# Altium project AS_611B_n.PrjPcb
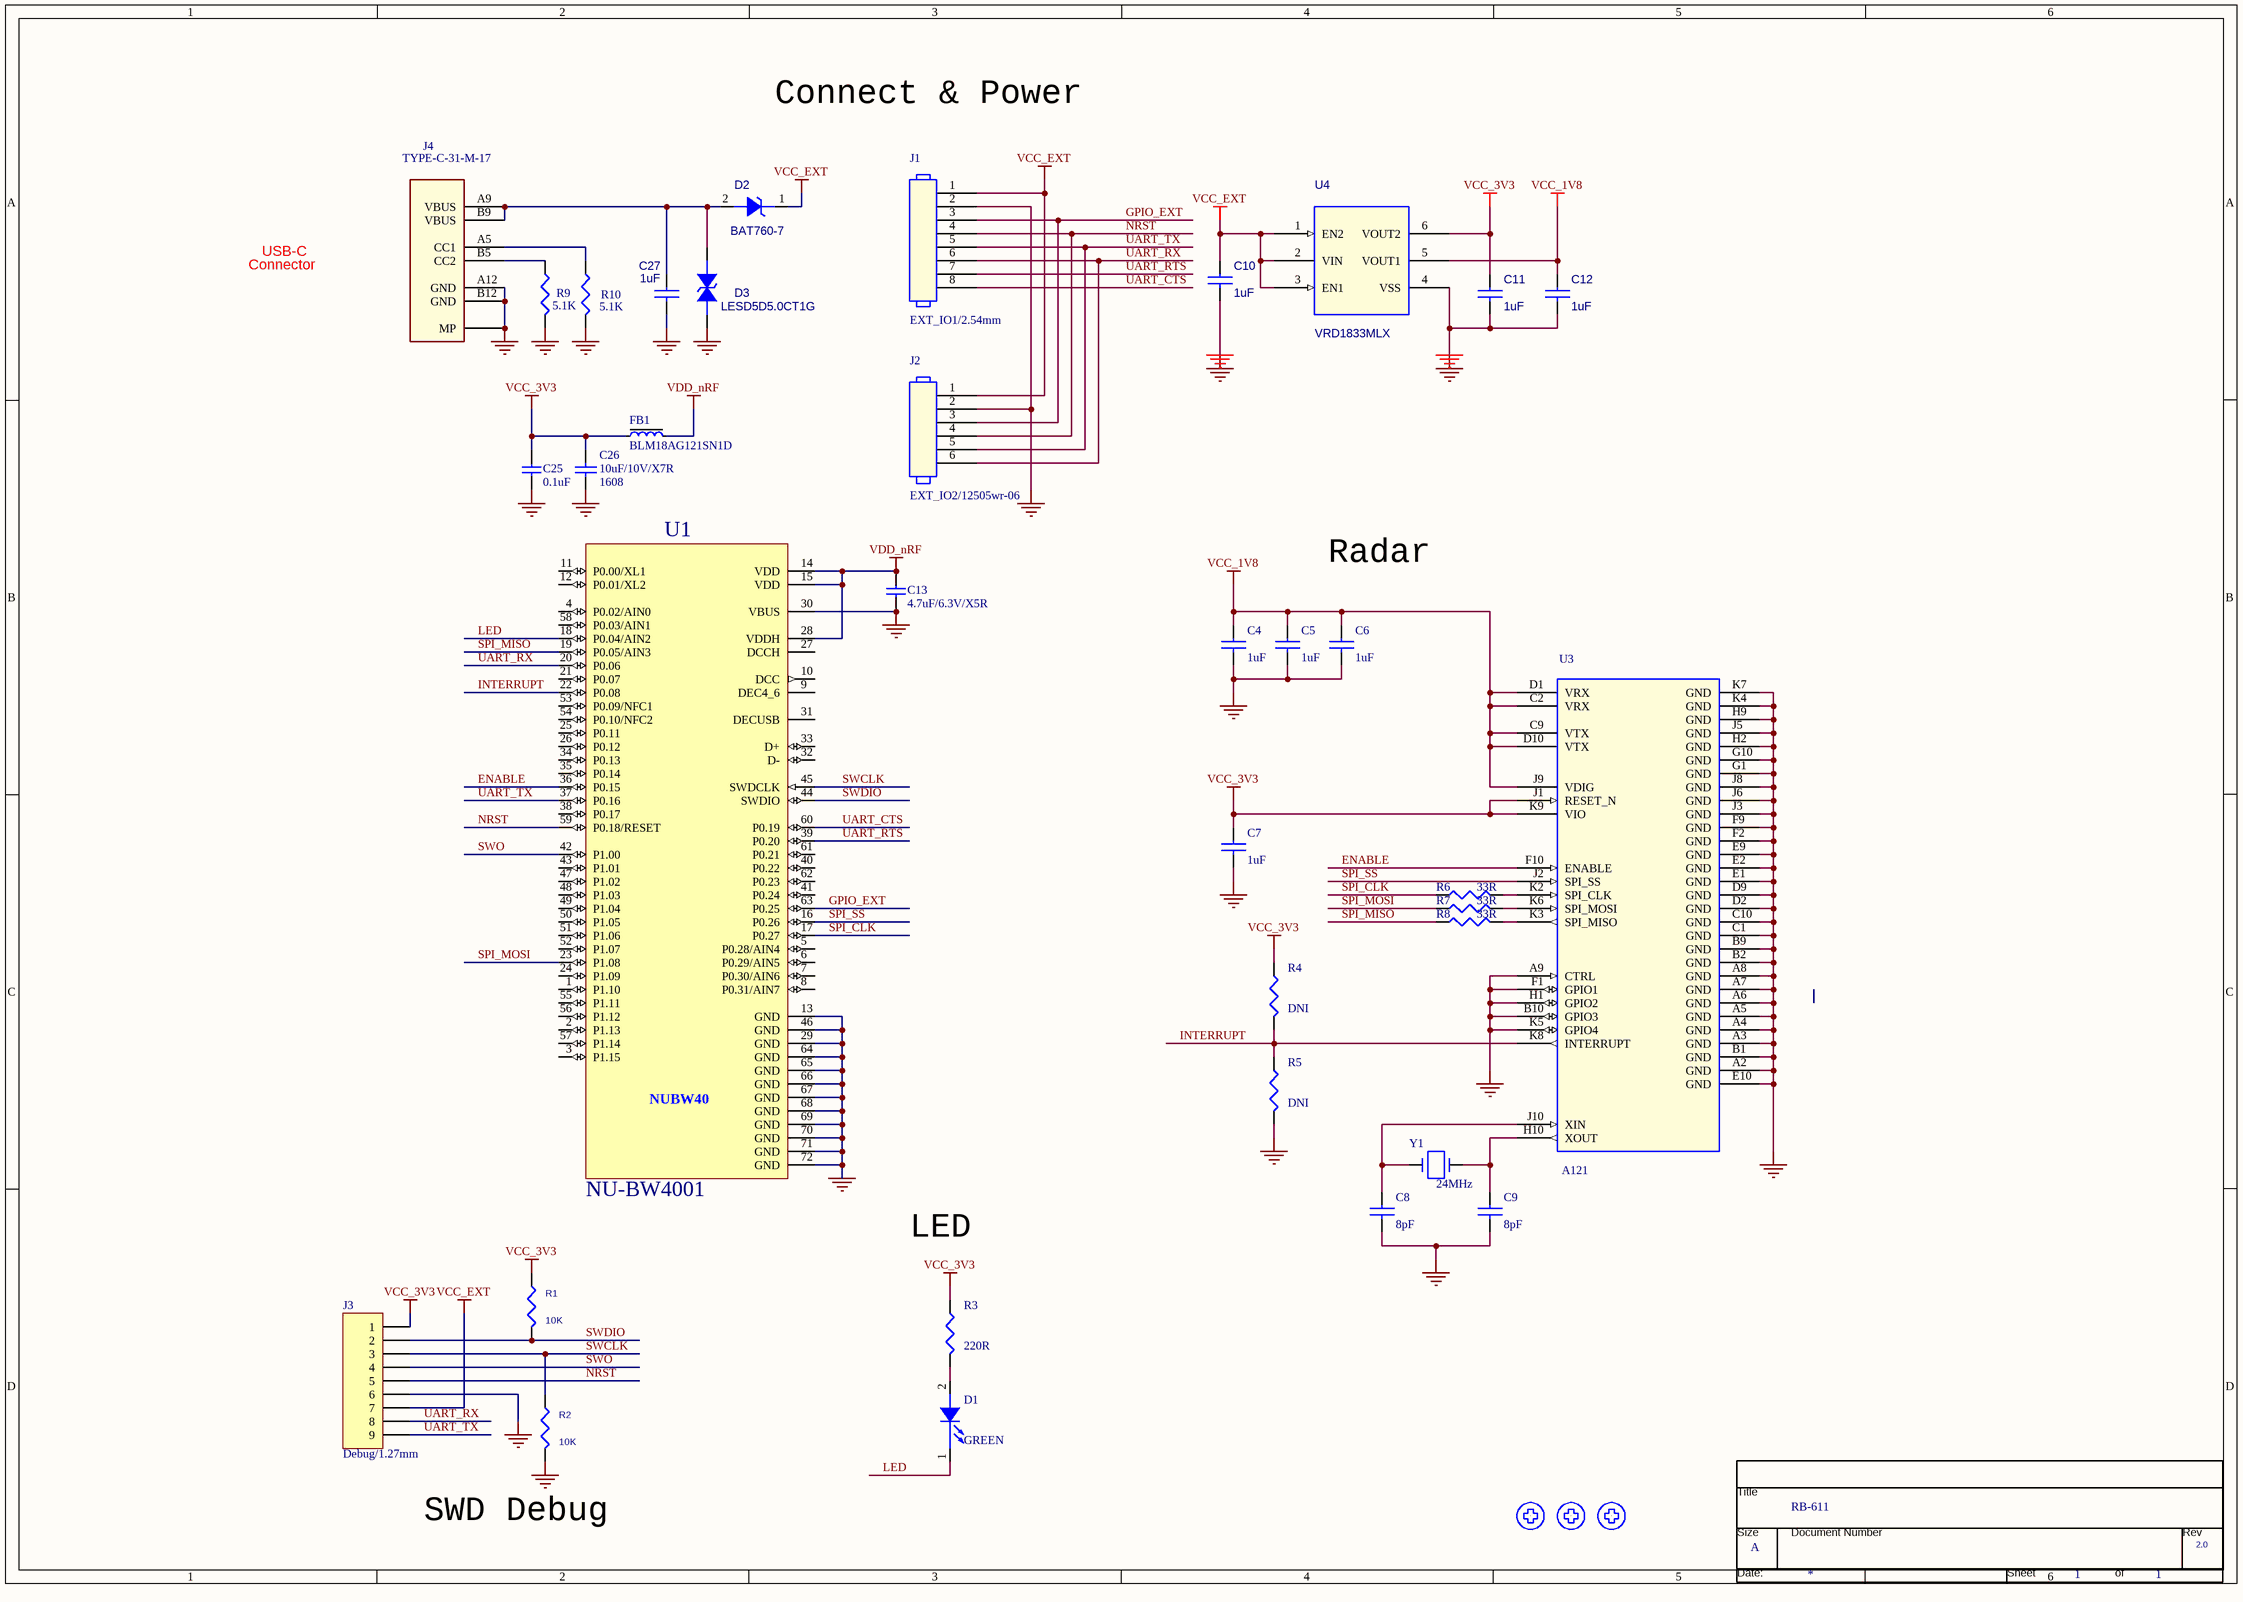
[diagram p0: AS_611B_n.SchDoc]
1 sheet, 39 parts. Net scope: global (net labels, ports and power ports of the same name join across sheets).
Board file: AS_611B_n.PcbDoc

## Sheet AS_611B_n.SchDoc
size 420 x 297 mm

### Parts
*  Page Count: 1  Page Size: A  Title: RB-611  RevCode: 2.0  (hidden comment: TitleBlock0)  (graphical)
C4  1uF  [CAP 0402/1005]
C5  1uF  [CAP 0402/1005]
C6  1uF  [CAP 0402/1005]
C7  1uF  [CAP 0402/1005]
C8  8pF  [CAP 0402/1005]
C9  8pF  [CAP 0402/1005]
C10  value 1uF  [CAP 0402/1005]  (hidden comment: CAP NP)
C11  value 1uF  [CAP 0402/1005]  (hidden comment: CAP NP)
C12  value 1uF  [CAP 0402/1005]  (hidden comment: CAP NP)
C13  4.7uF/6.3V/X5R  [CAP 0603/1608]
C25  0.1uF  [CAP 0402/1005]
C26  10uF/10V/X7R  PackageReference: 1608  [CAP 0603/1608]
C27  value 1uF  [CAP 0402/1005]  (hidden comment: CAP NP)
D1  GREEN  [LED 0603/1608 RED -21]
D2  value BAT760-7  [SOD-323 - 21]  (hidden comment: DIODE_POWER_0)
D3  value LESD5D5.0CT1G  [SOD523]  (hidden comment: DIODE BI-DIR TRIG)
FB1  BLM18AG121SN1D  [FER 0603/1608]
J1  EXT_IO1/2.54mm  [Pin Header 1x8 TH Pitch 2.54mm]
J2  EXT_IO2/12505wr-06  [12505WR-06/53261-0671]
J3  Debug/1.27mm  [PIN HEADER 1X9 TH 1.27mm]
J4  TYPE-C-31-M-17  [CON/USB-C/6P-1]
MT1  MOUNT HOLE  [MT-3 /HOLE]  (value not drawn)  (no BOM)
MT3  MOUNT HOLE  [MT-3 /HOLE]  (value not drawn)  (no BOM)
MT4  MOUNT HOLE  [MT-3 /HOLE]  (value not drawn)  (no BOM)
R1  value 10K  [RES 0402/1005]  (hidden comment: RESISTOR/SM)
R2  value 10K  [RES 0402/1005]  (hidden comment: RESISTOR/SM)
R3  220R  [RES 0402/1005]
R4  DNI  [RES 0402/1005]
R5  DNI  [RES 0402/1005]
R6  33R  [RES 0402/1005]
R7  33R  [RES 0402/1005]
R8  33R  [RES 0402/1005]
R9  5.1K  [RES 0402/1005]
R10  5.1K  [RES 0402/1005]
U1  NU-BW4001  [nu40]
U3  A121  [A111]
U4  VRD1833MLX  [LLP-6 / L2.0-W1.8-P0.50-BL-EP]
Y1  24MHz  [XTAL_3225]

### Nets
GND: C4.2 C5.2 C6.2 C7.2 C8.2 C9.2 C10.2 C11.2 C12.2 C13.2 C25.2 C26.1 C27.2 D3.2 J1.2 J2.2 J3.6 J4.A12(GND) J4.B12(GND) J4.MP R2.2 R5.2 R9.2 R10.2 U1.13(GND) U1.29(GND) U1.30(VBUS) U1.46(GND) U1.64(GND) U1.65(GND) U1.66(GND) U1.67(GND) U1.68(GND) U1.69(GND) U1.70(GND) U1.71(GND) U1.72(GND) U3.A2(GND) U3.A3(GND) U3.A4(GND) U3.A5(GND) U3.A6(GND) U3.A7(GND) U3.A8(GND) U3.A9(CTRL) U3.B1(GND) U3.B2(GND) U3.B9(GND) U3.B10(GPIO3) U3.C1(GND) U3.C10(GND) U3.D2(GND) U3.D9(GND) U3.E1(GND) U3.E2(GND) U3.E9(GND) U3.E10(GND) U3.F1(GPIO1) U3.F2(GND) U3.F9(GND) U3.G1(GND) U3.G10(GND) U3.H1(GPIO2) U3.H2(GND) U3.H9(GND) U3.J3(GND) U3.J5(GND) U3.J6(GND) U3.J8(GND) U3.K4(GND) U3.K5(GPIO4) U3.K7(GND) U4.4(VSS)
VCC_1V8: C4.1 C5.1 C6.1 C12.1 U3.C2(VRX) U3.C9(VTX) U3.D1(VRX) U3.D10(VTX) U3.J9(VDIG) U4.5(VOUT1)
VCC_3V3: C7.1 C11.1 C25.1 C26.2 FB1.2 J3.1 R1.1 R3.1 R4.1 U3.J1(RESET_N) U3.K9(VIO) U4.6(VOUT2)
VCC_EXT: C10.1 D2.1 J1.1 J2.1 J3.7 U4.1(EN2) U4.2(VIN) U4.3(EN1)
VDD_nRF: C13.1 FB1.1 U1.14(VDD) U1.15(VDD) U1.28(VDDH)
ENABLE: U1.36(P0.15) U3.F10(ENABLE)
GPIO_EXT: J1.3 J2.3 U1.63(P0.25)
INTERRUPT: R4.2 R5.1 U1.22(P0.08) U3.K8(INTERRUPT)
LED: D1.1(CATHODE) U1.18(P0.04/AIN2)
NRST: J1.4 J2.4 J3.5 U1.59(P0.18/RESET)
SPI_CLK: R6.1 U1.17(P0.27)
SPI_MISO: R8.1 U1.19(P0.05/AIN3)
SPI_MOSI: R7.1 U1.23(P1.08)
SPI_SS: U1.16(P0.26) U3.J2(SPI_SS)
SWCLK: J3.3 R2.1 U1.45(SWDCLK)
SWDIO: J3.2 R1.2 U1.44(SWDIO)
SWO: J3.4 U1.42(P1.00)
UART_CTS: J1.8 U1.60(P0.19)
UART_RTS: J1.7 U1.39(P0.20)
UART_RX: J1.6 J2.6 J3.8 U1.20(P0.06)
UART_TX: J1.5 J2.5 J3.9 U1.37(P0.16)
NetC8_1: C8.1 U3.J10(XIN) Y1.1
NetC9_1: C9.1 U3.H10(XOUT) Y1.3
NetC27_1: C27.1 D2.2 D3.1 J4.A9(VBUS) J4.B9(VBUS)
NetD1_2: D1.2(ANODE) R3.2
NetJ4_A5: J4.A5(CC1) R10.1
NetJ4_B5: J4.B5(CC2) R9.1
NetR6_2: R6.2 U3.K2(SPI_CLK)
NetR7_2: R7.2 U3.K6(SPI_MOSI)
NetR8_2: R8.2 U3.K3(SPI_MISO)

Not connected (* = marked no-connect by the designer): MT1 1; MT3 1; MT4 1; U1 1(P1.10) 2(P1.13) 3(P1.15) 4(P0.02/AIN0) 5(P0.28/AIN4) 6(P0.29/AIN5) 7(P0.30/AIN6) 8(P0.31/AIN7) 9(DEC4_6) 10(DCC) 11(P0.00/XL1) 12(P0.01/XL2) 21(P0.07) 24(P1.09) 25(P0.11) 26(P0.12) 27(DCCH) 31(DECUSB) 32(D-) 33(D+) 34(P0.13) 35(P0.14) 38(P0.17) 40(P0.22) 41(P0.24) 43(P1.01) 47(P1.02) 48(P1.03) 49(P1.04) 50(P1.05) 51(P1.06) 52(P1.07) 53(P0.09/NFC1) 54(P0.10/NFC2) 55(P1.11) 56(P1.12) 57(P1.14) 58(P0.03/AIN1) 61(P0.21) 62(P0.23)

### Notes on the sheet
- Connect & Power
- USB-C
- Connector
- Radar
- LED
- (near R2) SWD Debug

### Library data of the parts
C4-C9 = CAP NP
C10 = CAP NP: Part Reference: C10
C11 = CAP NP: Part Reference: C11
C12 = CAP NP: Part Reference: C12
C13 C25 = C0603-4µ7-6.3V-X7R: Capacitor, X7R, ±10%
C26 = Cap: MLCC
C27 = CAP NP: Part Reference: C1
D1 = LED
D2 = DIODE_POWER_0: Part Reference: D2; PCB Footprint: SOD323
D3 = DIODE BI-DIR TRIG: Part Reference: D3; Options: ESD; PCB Footprint: SOD-523
FB1 = FB0402-120R@100M-500mA: Ferrite Bead, 120 Ohm @ 100MHz, 500mA, 250 mOhm Max; Manufacturer: Murata; Manufacturer Part Number: BLM15AG121SN1D; Part number IPS: 00000009954; Note: Chip EMIFIL Inductor Type Chip Ferrite Bead; Artikkelnr Noca: 33029317
J1 = HEADER 8
J2 = HEADER 6
J3 = Header 9: Header, 9-Pin
J4 = CON/USB-C/6P: 6P C-type Connector; PCB DECAL: 20160406_T
MT1 MT3 MT4 = Mount Bolt
R1 R2 = RESISTOR/SM: Part Reference: R5
R3-R10 = RESISTOR/SM
U1 = nu40_1: BLE Module; Part Number: nRF52840-QIAAF0; Manufacturer: Nordic Semiconductor; Value: nRF52840-QIAA; Note: N.A.; Pad Count: 73
U4 = VRD1833MLX: Part Reference: U1
Y1 = CRYSTAL13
